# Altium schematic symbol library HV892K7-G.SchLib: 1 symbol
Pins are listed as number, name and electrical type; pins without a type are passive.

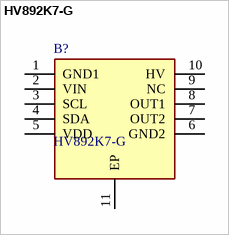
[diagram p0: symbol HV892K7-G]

## HV892K7-G
designator B?
Display Drivers & Controllers Inductorless Liquid Lens Driver; Manufacturer_Name: Microchip; Geometry.Height: 0.8mm
footprint SON65P400X400X80-11N-D
pins: 1 GND1, 2 VIN, 3 SCL, 4 SDA, 5 VDD, 6 GND2, 7 OUT2, 8 OUT1, 9 NC, 10 HV, 11 EP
